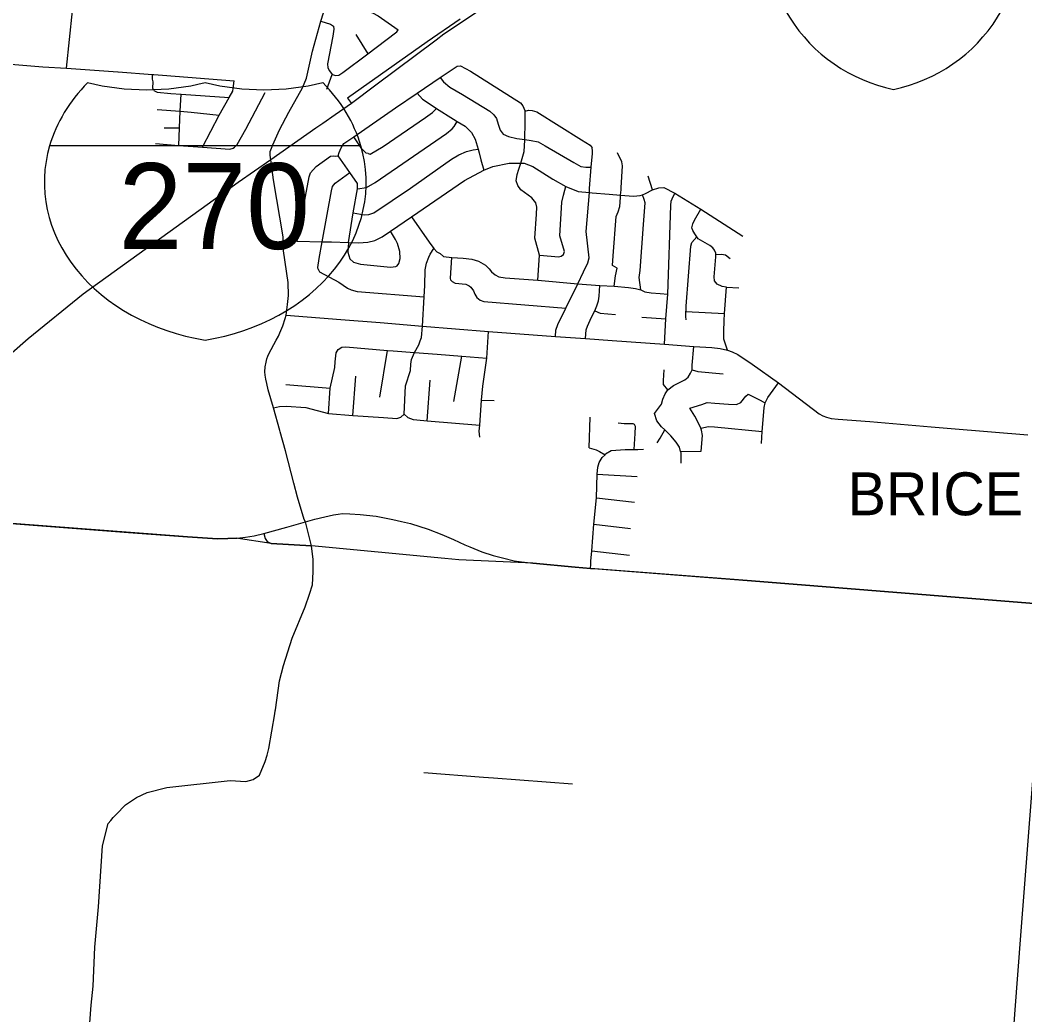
# Model space of a CAD drawing. Extents: x 1755200 to 1902939, y 644115 to 788070.
# Drawn here: x 1863214 to 1874924, y 692073 to 703665 of the extents above; entities that cross this region are included whole.
import ezdxf

# ---------------------------------------------------------------- set-up
doc = ezdxf.new("R2010")
doc.units = 0
for name, color, linetype in [('GM_X_City_Street', 7, 'Continuous'), ('GM_X_Corporation_Text', 7, 'Continuous'), ('GM_X_County_Road', 7, 'Continuous'), ('GM_X_Interchange_Ramps', 7, 'Continuous'), ('GM_X_Interstate_Route', 7, 'Continuous'), ('GM_X_Interstate_Shield', 7, 'Continuous'), ('GM_X_Township', 7, 'Continuous'), ('GM_X_Township_Road', 7, 'Continuous')]:
    doc.layers.add(name, color=color, linetype=linetype)

msp = doc.modelspace()

# ---------------------------------------------------------------- linework, layer by layer
at = {"layer": 'GM_X_City_Street'}
for points in [[(1863756, 703103), (1863858, 704109), (1863885, 704529), (1863926, 704981)], [(1866244, 698866), (1866239, 698881), (1866165, 699146), (1866104, 699357), (1866088, 699432), (1866078, 699480), (1866071, 699526), (1866067, 699566), (1866070, 699624), (1866080, 699680), (1866091, 699717), (1866100, 699747), (1866111, 699776), (1866198, 699935), (1866225, 699983), (1866241, 700019), (1866275, 700104), (1866304, 700186), (1866315, 700228), (1866332, 700349), (1866343, 700456), (1866339, 700609), (1866285, 700975), (1866281, 701095), (1866280, 701141), (1866165, 701802), (1866135, 702037), (1866129, 702091), (1866129, 702135), (1866159, 702213), (1866238, 702385), (1866347, 702593), (1866503, 702877), (1866553, 702987), (1866582, 703126), (1866621, 703304), (1866720, 703653), (1866807, 703934)], [(1866807, 703934), (1867074, 703841), (1867322, 703751), (1867387, 703716), (1867619, 703553)], [(1866720, 703653), (1866830, 703617), (1866865, 703594), (1866871, 703558), (1866859, 703478), (1866797, 703155), (1866802, 703107), (1866819, 703072), (1866850, 703031)], [(1866850, 703031), (1866894, 703020), (1866930, 703024), (1866976, 703053), (1867267, 703273), (1867590, 703517), (1867606, 703527), (1867619, 703553)], [(1867127, 703495), (1867267, 703273)], [(1862116, 703231), (1863479, 703122), (1863756, 703103), (1864353, 703060), (1864355, 703060)], [(1866921, 702082), (1866932, 702122), (1866955, 702177), (1866988, 702225), (1867102, 702304), (1867587, 702642), (1867843, 702815), (1868110, 702994), (1868273, 703105), (1868307, 703128), (1868345, 703131), (1868464, 703069), (1869047, 702702), (1869074, 702665), (1869086, 702639), (1869099, 702603)], [(1864355, 703060), (1864758, 703032), (1864770, 703031), (1864772, 703031)], [(1864773, 702845), (1864759, 702870), (1864763, 702946), (1864757, 702978), (1864758, 703032)], [(1864772, 703031), (1864874, 703024), (1865709, 702958)], [(1866787, 702858), (1866850, 703031)], [(1868110, 702994), (1868150, 702947), (1868222, 702883), (1868368, 702798), (1868688, 702603), (1868733, 702562), (1868764, 702517), (1868785, 702451), (1868809, 702382), (1868844, 702335), (1868907, 702308), (1869003, 702286), (1869098, 702272), (1869168, 702263), (1869250, 702245), (1869334, 702199), (1869668, 702006), (1869749, 701960), (1869807, 701953), (1869871, 701950)], [(1865340, 702184), (1865535, 702557), (1865651, 702761), (1865692, 702835), (1865697, 702869), (1865709, 702958)], [(1864773, 702845), (1864810, 702824), (1864969, 702809), (1865089, 702801), (1865651, 702761)], [(1865063, 702205), (1865072, 702408), (1865080, 702602), (1865089, 702801)], [(1865711, 702183), (1865744, 702214), (1865843, 702395), (1866071, 702821)], [(1867843, 702815), (1867902, 702745), (1868015, 702669), (1868068, 702635), (1868263, 702510), (1868306, 702484), (1868401, 702427), (1868475, 702355), (1868518, 702276), (1868552, 702159), (1868564, 702119), (1868583, 702036), (1868619, 701917)], [(1864812, 702622), (1865080, 702602), (1865209, 702592), (1865535, 702557)], [(1867269, 702109), (1867295, 702104), (1867446, 702190), (1867940, 702528), (1868021, 702587), (1868068, 702635)], [(1869246, 700633), (1869266, 700925), (1869213, 701123), (1869233, 701402), (1869236, 701484), (1869225, 701536), (1869177, 701595), (1869051, 701686), (1869014, 701737), (1868997, 701793), (1869008, 701865), (1869028, 701929), (1869048, 701996), (1869049, 701998), (1869090, 702132), (1869098, 702264), (1869098, 702272), (1869100, 702474), (1869100, 702567), (1869099, 702603)], [(1869099, 702603), (1869139, 702616), (1869183, 702613), (1869235, 702594), (1869757, 702271), (1869858, 702208), (1869869, 702190), (1869881, 702176)], [(1864892, 702410), (1865072, 702408)], [(1867145, 701697), (1867251, 701715), (1867352, 701771), (1868182, 702345), (1868251, 702396), (1868271, 702425), (1868306, 702484)], [(1867269, 702109), (1867245, 702113), (1867196, 702165), (1867102, 702304)], [(1864792, 702226), (1865063, 702205), (1865340, 702184), (1865657, 702162), (1865695, 702173), (1865711, 702183)], [(1869453, 699978), (1869459, 700050), (1869482, 700117), (1869574, 700309), (1869715, 700593), (1869778, 700730), (1869831, 700835), (1869845, 700894), (1869811, 701203), (1869848, 701654), (1869851, 701702), (1869871, 701950), (1869884, 702112), (1869884, 702140), (1869881, 702176)], [(1866442, 701090), (1866583, 701840), (1866598, 701884), (1866665, 701959), (1866833, 702080), (1866867, 702085), (1866889, 702081), (1866921, 702082)], [(1867040, 701074), (1867095, 701419), (1867145, 701697), (1867144, 701759), (1867058, 701889), (1866921, 702082)], [(1867095, 701419), (1867224, 701396), (1867278, 701399), (1867337, 701420), (1867762, 701708), (1868241, 702043), (1868326, 702095), (1868417, 702134), (1868493, 702152), (1868552, 702159)], [(1870217, 701687), (1870218, 701709), (1870236, 701966), (1870225, 702013), (1870177, 702120)], [(1866281, 701095), (1866442, 701090), (1866735, 701082), (1866841, 701080), (1867040, 701074), (1867156, 701071), (1867268, 701079), (1867346, 701095), (1867435, 701140), (1867531, 701206), (1867774, 701372), (1868394, 701797), (1868619, 701917), (1868723, 701957), (1868915, 701999), (1869048, 701996), (1869087, 701996), (1869188, 701958), (1869421, 701813), (1869574, 701725), (1869717, 701666), (1869848, 701654), (1869880, 701651), (1870078, 701635), (1870212, 701625), (1870363, 701615), (1870439, 701619), (1870468, 701630), (1870501, 701643)], [(1866689, 700762), (1866683, 700782), (1866699, 700888), (1866735, 701082), (1866843, 701677), (1866856, 701725), (1866885, 701764), (1867058, 701889)], [(1870585, 701688), (1870535, 701846)], [(1869547, 700933), (1869560, 700967), (1869503, 701150), (1869529, 701542), (1869546, 701624), (1869562, 701683), (1869574, 701725)], [(1870501, 701643), (1870502, 701643), (1870585, 701688), (1870656, 701711), (1870718, 701714), (1870846, 701647), (1871149, 701460), (1871637, 701146)], [(1870137, 700563), (1870153, 700684), (1870171, 700776), (1870117, 700804), (1870127, 700918), (1870162, 701375), (1870183, 701430), (1870202, 701492), (1870211, 701598), (1870212, 701625), (1870217, 701687)], [(1870449, 700520), (1870429, 700664), (1870441, 700746), (1870478, 701282), (1870497, 701536), (1870488, 701576), (1870468, 701630)], [(1870722, 699888), (1870739, 700182), (1870763, 700473), (1870798, 701506), (1870803, 701556), (1870813, 701584), (1870846, 701647)], [(1867774, 701372), (1867983, 701078), (1868035, 701005), (1868072, 700964), (1868108, 700944), (1868149, 700911), (1868247, 700899), (1868376, 700889), (1868479, 700880), (1868555, 700857), (1868638, 700809), (1868679, 700767), (1868707, 700730), (1868749, 700696), (1868792, 700672), (1868868, 700663), (1869246, 700633), (1869715, 700593), (1869969, 700572), (1870137, 700563), (1870303, 700548), (1870385, 700537), (1870449, 700520), (1870496, 700499), (1870570, 700487), (1870672, 700479), (1870763, 700473)], [(1871447, 700551), (1871397, 700562), (1871338, 700589), (1871307, 700626), (1871302, 700674), (1871323, 700908), (1871322, 700934), (1871321, 700948), (1871308, 700984), (1871287, 701011), (1871253, 701040), (1871117, 701117), (1871101, 701141), (1871078, 701176), (1871055, 701214), (1871042, 701246), (1871055, 701290), (1871074, 701334), (1871149, 701460)], [(1867608, 700803), (1867626, 700827), (1867643, 700885), (1867641, 700967), (1867613, 701060), (1867588, 701108), (1867531, 701206)], [(1870974, 700272), (1870975, 700273), (1870978, 700332), (1871032, 701032), (1871044, 701072), (1871101, 701141)], [(1867040, 701074), (1867034, 700959), (1867056, 700883), (1867100, 700844), (1867179, 700820), (1867530, 700787), (1867592, 700794), (1867608, 700803)], [(1867689, 699074), (1867705, 699405), (1867764, 699580), (1867769, 699656), (1867777, 699710), (1867811, 699792), (1867859, 699882), (1867878, 699928), (1867890, 699967), (1867902, 700098), (1867921, 700440), (1867930, 700572), (1867936, 700755), (1867950, 700831), (1867977, 700904), (1867994, 700938), (1868035, 701005)], [(1868250, 700617), (1868235, 700634), (1868228, 700658), (1868247, 700899)], [(1869266, 700925), (1869492, 700907), (1869519, 700913), (1869547, 700933)], [(1871322, 700934), (1871389, 700939), (1871433, 700930), (1871490, 700887)], [(1866689, 700762), (1866704, 700732), (1866930, 700611), (1867028, 700540), (1867074, 700521), (1867143, 700501), (1867921, 700440)], [(1868250, 700617), (1868285, 700601), (1868407, 700589), (1868447, 700570), (1868466, 700554), (1868497, 700510), (1868514, 700473), (1868537, 700432), (1868574, 700400), (1868618, 700384), (1869574, 700309)], [(1869805, 699953), (1869812, 700054), (1869827, 700100), (1869875, 700203), (1869913, 700276), (1869935, 700334), (1869956, 700394), (1869962, 700447), (1869969, 700572)], [(1871424, 700234), (1871424, 700236), (1871425, 700246), (1871447, 700551)], [(1871447, 700551), (1871591, 700544)], [(1866315, 700228), (1866953, 700178), (1867411, 700140), (1867902, 700098), (1868674, 700037), (1869453, 699978), (1869805, 699953), (1870113, 699931), (1870722, 699888), (1871065, 699862), (1871277, 699848), (1871371, 699838), (1871460, 699819), (1871514, 699800), (1871580, 699770), (1871747, 699655), (1872052, 699438), (1872525, 699078), (1872570, 699053), (1872613, 699038), (1872668, 699024), (1872748, 699013), (1873117, 698986), (1873833, 698927), (1874063, 698907)], [(1869913, 700276), (1869975, 700249), (1870151, 700233)], [(1870459, 700203), (1870739, 700182)], [(1870978, 700174), (1870971, 700210), (1870974, 700268), (1870974, 700272)], [(1870974, 700268), (1871425, 700246)], [(1871460, 699819), (1871415, 699946), (1871415, 700030), (1871420, 700173), (1871424, 700234)], [(1868572, 698806), (1868565, 698876), (1868570, 698945), (1868593, 699236), (1868606, 699398), (1868653, 699725), (1868674, 700037)], [(1866922, 699827), (1866964, 699853), (1867010, 699856), (1867496, 699815), (1867561, 699811), (1867811, 699792), (1868074, 699771), (1868363, 699747), (1868653, 699725)], [(1870917, 698502), (1870917, 698622), (1870912, 698639), (1870897, 698688), (1870860, 698747), (1870799, 698819), (1870727, 698889), (1870690, 698925), (1870633, 698996), (1870607, 699079), (1870690, 699188), (1870705, 699246), (1870731, 699310), (1870762, 699355), (1870830, 699409), (1870960, 699473), (1871000, 699505), (1871028, 699550), (1871046, 699590), (1871048, 699643), (1871065, 699862)], [(1866807, 699079), (1866829, 699375), (1866881, 699616), (1866885, 699683), (1866888, 699719), (1866899, 699787), (1866922, 699827)], [(1867407, 699273), (1867496, 699815)], [(1868267, 699221), (1868363, 699747)], [(1867092, 699059), (1867127, 699515)], [(1870762, 699355), (1870711, 699419), (1870712, 699467), (1870719, 699588)], [(1871046, 699590), (1871114, 699571), (1871407, 699543)], [(1866312, 699417), (1866829, 699375)], [(1867957, 698996), (1867992, 699471)], [(1871853, 698732), (1871863, 698871), (1871873, 699006), (1871885, 699149), (1871899, 699206), (1871927, 699266), (1872052, 699438)], [(1871020, 699143), (1871158, 699184), (1871223, 699208), (1871311, 699203), (1871468, 699190), (1871564, 699185), (1871614, 699209), (1871672, 699281), (1871699, 699307), (1871745, 699283), (1871815, 699246), (1871899, 699206)], [(1866165, 699146), (1866236, 699163), (1866313, 699167), (1866542, 699151), (1866807, 699079), (1867092, 699059), (1867450, 699033), (1867606, 699022), (1867650, 699039), (1867689, 699074)], [(1868593, 699236), (1868740, 699231)], [(1871153, 698643), (1871165, 698825), (1871156, 698886), (1871148, 698910), (1871141, 698928), (1871078, 699051), (1871020, 699143)], [(1867689, 699074), (1867734, 699033), (1867793, 699010), (1867919, 699000), (1867957, 698996), (1868570, 698945)], [(1869845, 698682), (1869856, 699040)], [(1870371, 698662), (1870381, 698847), (1870385, 698931), (1870375, 698954), (1870357, 698960), (1870325, 698961), (1870253, 698962), (1870184, 698967)], [(1871148, 698910), (1871237, 698928), (1871307, 698927), (1871863, 698871)], [(1874063, 698907), (1874957, 698831)], [(1866550, 697772), (1866538, 697818), (1866524, 697845), (1866448, 698105), (1866404, 698269), (1866307, 698645), (1866244, 698866)], [(1870639, 698739), (1870674, 698795), (1870727, 698889)], [(1869845, 698682), (1869926, 698658), (1869965, 698637), (1870031, 698601)], [(1870031, 698601), (1870037, 698610), (1870102, 698650), (1870267, 698663), (1870371, 698662), (1870414, 698663), (1870480, 698666)], [(1869861, 697276), (1869864, 697323), (1869867, 697360), (1869878, 697481), (1869902, 697791), (1869931, 698097), (1869938, 698375), (1869948, 698457), (1869963, 698511), (1869998, 698568), (1870031, 698601)], [(1870912, 698639), (1871153, 698643)], [(1869938, 698375), (1870407, 698346)], [(1869931, 698097), (1870375, 698046)], [(1862259, 697869), (1862555, 697842), (1864476, 697696)], [(1869902, 697791), (1870329, 697740)], [(1869878, 697481), (1870316, 697430)], [(1869895, 697274), (1871736, 697131), (1875175, 696856)], [(1874409, 686478), (1874480, 687499), (1874558, 688592), (1874608, 689305), (1874622, 689526), (1874627, 689590), (1874698, 690594), (1874737, 691097), (1874807, 692083), (1874880, 693048), (1875039, 695102), (1875078, 695560), (1875115, 696086), (1875158, 696658), (1875175, 696856)]]:
    msp.add_lwpolyline(points, dxfattribs=at)
at = {"layer": 'GM_X_County_Road'}
for points in [[(1866538, 697818), (1866649, 697848), (1866766, 697876), (1866866, 697900), (1866920, 697909), (1866973, 697914), (1867058, 697913), (1867177, 697905), (1867362, 697883), (1867559, 697847), (1867659, 697824), (1867763, 697798), (1867969, 697733), (1868127, 697672), (1868265, 697613), (1868398, 697552), (1868456, 697526), (1868503, 697506), (1868595, 697469), (1868727, 697427), (1868853, 697394), (1868971, 697366), (1869057, 697354), (1869162, 697341)], [(1865743, 697629), (1865841, 697641), (1865943, 697657), (1866056, 697684), (1866321, 697756), (1866538, 697818)], [(1866610, 697540), (1866550, 697772)], [(1864476, 697696), (1865166, 697644), (1865514, 697621), (1865633, 697623), (1865732, 697627), (1865743, 697629)], [(1866628, 697235), (1866629, 697236), (1866630, 697380), (1866610, 697540)], [(1869162, 697341), (1869190, 697337), (1869683, 697291), (1869861, 697276), (1869895, 697274)], [(1866188, 695618), (1866190, 695628), (1866235, 695967), (1866282, 696143), (1866385, 696462), (1866535, 696827), (1866587, 696977), (1866621, 697084), (1866628, 697235)], [(1863994, 691569), (1864043, 692185), (1864064, 692410), (1864085, 692862), (1864126, 693333), (1864175, 694045), (1864241, 694305), (1864273, 694340), (1864297, 694374), (1864332, 694409), (1864441, 694522), (1864570, 694605), (1864693, 694666), (1864923, 694722), (1865662, 694803), (1865844, 694792), (1865929, 694818), (1866002, 694868), (1866070, 695025), (1866092, 695101), (1866114, 695176), (1866182, 695583), (1866188, 695618)]]:
    msp.add_lwpolyline(points, dxfattribs=at)
at = {"layer": 'GM_X_Interchange_Ramps'}
msp.add_lwpolyline([(1868344, 703676), (1867957, 703413), (1867030, 702754), (1867075, 702693)], dxfattribs=at)
at = {"layer": 'GM_X_Interstate_Route'}
for points in [[(1868673, 703846), (1868673, 703846), (1868154, 703499), (1868062, 703430)], [(1868062, 703430), (1867360, 702905), (1867075, 702693)], [(1867075, 702693), (1866887, 702562)], [(1866887, 702562), (1866740, 702459), (1866661, 702405)], [(1866661, 702405), (1866135, 702037), (1865754, 701771), (1863948, 700473), (1863307, 699951), (1863118, 699783), (1862753, 699455), (1862463, 699181), (1861921, 698685), (1861760, 698527)]]:
    msp.add_lwpolyline(points, dxfattribs=at)
at = {"layer": 'GM_X_Interstate_Shield'}
msp.add_line((1867184, 702201), (1863558, 702201), dxfattribs=at)
msp.add_line((1867184, 702201), (1863558, 702201), dxfattribs=at)
for centre, start, end in [((1873768, 704695), 165.8066, 258.463), ((1873018, 704695), 281.537, 14.1934)]:
    msp.add_arc(centre, 1875, start, end, dxfattribs=at)
for centre, start_param, end_param in [((1865840, 701773), 2.47259, 2.911027), ((1864686, 704729), 4.415841, 5.008937), ((1866056, 704729), 4.415841, 5.008937), ((1864903, 701773), 0.230566, 0.669003), ((1865840, 701773), 2.911027, 4.511031), ((1864903, 701773), 4.913747, 6.513751)]:
    msp.add_ellipse(centre, major_axis=(2344, 0), ratio=0.8, start_param=start_param, end_param=end_param, dxfattribs=at)
at = {"layer": 'GM_X_Township'}
msp.add_lwpolyline([(1875175, 696856), (1871736, 697131), (1869861, 697276), (1869683, 697291), (1869190, 697337), (1868327, 697375), (1868165, 697391), (1866610, 697540), (1866139, 697568), (1865732, 697627), (1865633, 697623), (1865514, 697621), (1865166, 697644), (1862555, 697842), (1861818, 697909), (1861731, 697912), (1861625, 697914), (1861145, 697954), (1857989, 698197), (1857145, 698259), (1855252, 698403), (1851851, 698657)], dxfattribs=at)
at = {"layer": 'GM_X_Township_Road'}
for points in [[(1866056, 697684), (1866071, 697623), (1866094, 697589), (1866139, 697568), (1866610, 697540)], [(1867918, 694897), (1868614, 694845), (1868731, 694836), (1868731, 694836)], [(1868731, 694836), (1869653, 694767)]]:
    msp.add_lwpolyline(points, dxfattribs=at)

# ---------------------------------------------------------------- texts
at = {"layer": 'GM_X_Corporation_Text'}
msp.add_text('BRICE', height=500, rotation=0, dxfattribs=at).set_placement((1872859, 697895))
at = {"layer": 'GM_X_Interstate_Shield'}
msp.add_text('270', height=1000, dxfattribs=at).set_placement((1864361, 700998))

doc.saveas('drawing.dxf')
